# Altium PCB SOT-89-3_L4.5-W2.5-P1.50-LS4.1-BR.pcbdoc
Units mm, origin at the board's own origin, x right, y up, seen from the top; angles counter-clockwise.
Board outline 17.9 x 17.61 mm, 2 copper layers (Top Layer, Bottom Layer), stack 0.07 mm thick; 1 components, 0 nets, 4 pads, 0 vias.
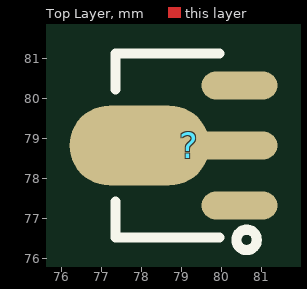
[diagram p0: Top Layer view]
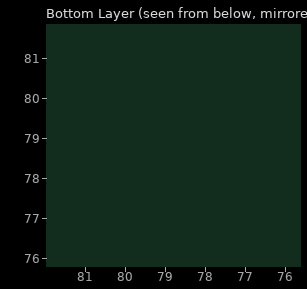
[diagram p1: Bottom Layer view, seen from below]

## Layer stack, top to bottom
Top Solder Mask Layer: solder mask 0.01, Dk 3.3
Top Layer: signal copper 0.035
Bottom Layer: signal copper 0.035
Bottom Solder Mask Layer: solder mask 0.01, Dk 3.3

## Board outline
87.75,69.85 69.85,69.85 69.85,87.465 87.75,87.465

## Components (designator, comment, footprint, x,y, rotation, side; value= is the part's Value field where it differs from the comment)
? "SOT-89-3_L4.5-W2.5-P1.50-LS4.1-BR" SOT-89-3_L4.5-W2.5-P1.50-LS4.1-BR 79.2,78.815 r0 top

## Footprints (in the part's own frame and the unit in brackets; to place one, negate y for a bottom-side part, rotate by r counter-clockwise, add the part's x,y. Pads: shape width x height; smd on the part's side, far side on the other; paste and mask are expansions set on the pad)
SOT-89-3_L4.5-W2.5-P1.50-LS4.1-BR [mm]
  oval 1.9x0.7 smd paste-100 mask+0.051: 1(1.25,-1.501) 3(1.25,1.501)
  oval 3.5x2 smd paste-100 mask+0.051: 2(-1.25,0)
  oval 2.1x0.7 smd paste-100 mask+0.051: 2(1.151,0)
  silkscreen extent -1.85,-2.61 1.68,2.3

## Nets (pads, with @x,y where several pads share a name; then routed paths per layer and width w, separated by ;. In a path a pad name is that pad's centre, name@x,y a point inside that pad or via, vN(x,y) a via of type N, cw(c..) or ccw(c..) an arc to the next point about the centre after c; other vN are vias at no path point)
pads on no net: ?.1 ?.2 ?.3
